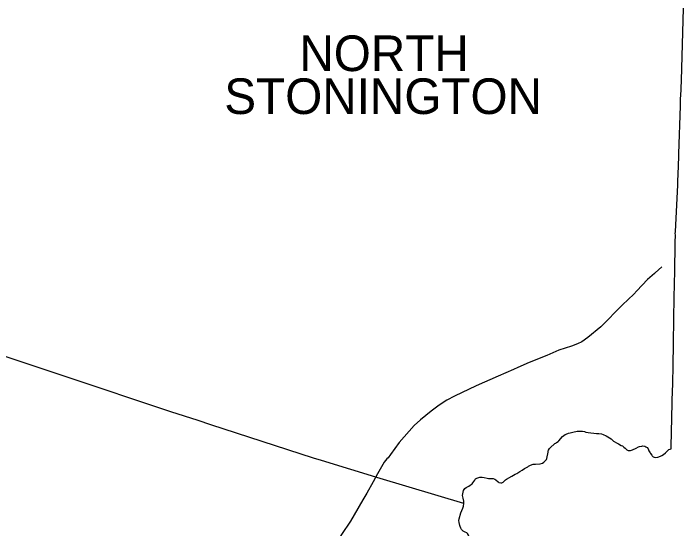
# Model space of a CAD drawing. Extents: x 0 to 2603, y -226 to 830.
# Drawn here: x 335.14 to 360.53, y 555.47 to 575 of the extents above; entities that cross this region are included whole.
import ezdxf

# ---------------------------------------------------------------- set-up
doc = ezdxf.new("R2010")
doc.units = 0
for name, color, linetype in [('CT_TSH_Map_Interstate_Roads', 7, 'Continuous'), ('CT_TSH_Map_Town_Limits', 7, 'Continuous'), ('CT_TSH_Map_Town_Text', 7, 'Continuous')]:
    doc.layers.add(name, color=color, linetype=linetype)

msp = doc.modelspace()

# ---------------------------------------------------------------- linework, layer by layer
at = {"layer": 'CT_TSH_Map_Interstate_Roads'}
for points in [[(359.7, 565.398), (359.443, 565.161)], [(359.418, 565.136), (359.163, 564.91)], [(359.443, 565.161), (359.418, 565.136)], [(359.163, 564.91), (358.756, 564.484)], [(358.756, 564.484), (358.636, 564.358)], [(358.636, 564.358), (358.209, 563.951), (357.386, 563.121), (356.902, 562.709)], [(356.902, 562.709), (356.667, 562.552)], [(356.504, 562.475), (356.283, 562.39), (355.797, 562.233), (355.343, 562.033), (354.681, 561.761), (354.249, 561.577)], [(356.667, 562.552), (356.504, 562.475)], [(354.249, 561.577), (354.077, 561.497), (353.501, 561.254), (352.668, 560.887), (351.846, 560.488)], [(351.846, 560.488), (351.558, 560.338), (351.267, 560.147)], [(351.267, 560.147), (350.959, 559.919), (350.555, 559.596)], [(350.555, 559.596), (350.323, 559.377)], [(350.323, 559.377), (349.748, 558.73), (349.425, 558.287), (349.338, 558.157)], [(349.338, 558.157), (349.286, 558.119), (349.185, 557.986)], [(349.185, 557.986), (348.929, 557.546)], [(348.929, 557.546), (348.762, 557.25), (348.523, 556.811)], [(348.523, 556.811), (348.38, 556.557), (348.05, 556)], [(348.05, 556), (347.903, 555.761), (347.571, 555.245), (347.381, 554.938), (347.147, 554.608)]]:
    msp.add_lwpolyline(points, dxfattribs=at)
at = {"layer": 'CT_TSH_Map_Town_Limits'}
for points in [[(358.974, 558.607), (359.059, 558.599), (359.101, 558.577), (359.142, 558.544), (359.177, 558.498), (359.209, 558.425), (359.256, 558.349), (359.269, 558.318), (359.325, 558.257), (359.337, 558.23), (359.354, 558.205), (359.375, 558.189), (359.411, 558.174), (359.458, 558.169), (359.547, 558.178), (359.651, 558.214), (359.696, 558.245), (359.769, 558.286), (359.844, 558.339), (359.9, 558.41), (359.923, 558.428), (359.961, 558.472), (360.016, 558.489), (360.056, 558.497), (360.058, 558.549), (360.055, 558.589), (360.106, 560.771), (360.114, 560.861), (360.128, 561.773), (360.143, 562.36), (360.141, 562.478), (360.149, 562.523), (360.15, 563.385), (360.157, 563.501), (360.178, 564.807), (360.191, 565.167), (360.206, 566.319), (360.217, 566.61), (360.212, 566.652), (360.225, 566.724), (360.313, 568.504), (360.311, 568.655), (360.324, 568.891), (360.345, 569.57), (360.339, 569.6), (360.349, 569.67), (360.405, 571.494), (360.414, 571.623), (360.414, 571.754), (360.409, 571.799), (360.416, 571.86), (360.442, 572.459), (360.525, 575.194)], [(352.196, 556.418), (349.026, 557.372), (346.803, 558.055), (346.503, 558.148), (342.62, 559.406), (342.136, 559.565), (341.106, 559.901), (337.099, 561.235), (334.314, 562.16)], [(352.196, 556.418), (352.198, 556.458), (352.194, 556.513), (352.171, 556.626), (352.154, 556.729), (352.171, 556.854), (352.192, 556.913), (352.211, 556.954), (352.239, 556.997), (352.29, 557.036), (352.384, 557.082), (352.438, 557.12), (352.484, 557.145), (352.521, 557.174), (352.536, 557.206), (352.618, 557.303), (352.648, 557.354), (352.694, 557.389), (352.804, 557.422), (352.844, 557.425), (352.896, 557.421), (352.968, 557.404), (352.974, 557.404), (353.09, 557.384), (353.129, 557.377), (353.268, 557.372), (353.305, 557.37), (353.37, 557.351), (353.409, 557.321), (353.501, 557.24), (353.53, 557.219), (353.599, 557.203), (353.642, 557.211), (353.689, 557.234), (353.776, 557.316), (353.819, 557.346), (354.024, 557.458), (354.148, 557.536), (354.21, 557.561), (354.317, 557.64), (354.409, 557.688), (354.493, 557.745), (354.621, 557.818), (354.656, 557.835), (354.697, 557.865), (354.793, 557.907), (354.831, 557.919), (354.918, 557.919), (355.092, 557.931), (355.176, 557.954), (355.232, 557.992), (355.316, 558.077), (355.33, 558.096), (355.348, 558.135), (355.394, 558.366), (355.397, 558.402), (355.406, 558.444), (355.444, 558.51), (355.5, 558.561), (355.626, 558.669), (355.652, 558.695), (355.682, 558.716), (355.712, 558.73), (355.774, 558.775), (355.805, 558.801), (355.944, 558.963), (356.045, 559.038), (356.134, 559.078), (356.166, 559.09), (356.225, 559.099), (356.329, 559.13), (356.496, 559.159), (356.597, 559.169), (356.699, 559.168), (356.77, 559.154), (356.827, 559.132), (356.904, 559.113), (357.227, 559.076), (357.313, 559.075), (357.418, 559.058), (357.481, 559.04), (357.595, 558.993), (357.778, 558.869), (357.796, 558.86), (357.876, 558.788), (358.003, 558.711), (358.064, 558.682), (358.157, 558.627), (358.212, 558.604), (358.264, 558.557), (358.313, 558.522), (358.373, 558.464), (358.395, 558.449), (358.428, 558.436), (358.508, 558.438), (358.59, 558.462), (358.734, 558.526), (358.814, 558.57), (358.859, 558.587), (358.938, 558.6), (358.974, 558.607)], [(352.41, 554.809), (352.396, 554.949), (352.394, 555.05), (352.386, 555.186), (352.376, 555.219), (352.337, 555.291), (352.316, 555.309), (352.246, 555.336), (352.179, 555.377), (352.113, 555.444), (352.085, 555.492), (352.065, 555.547), (352.054, 555.594), (352.02, 555.702), (352.016, 555.786), (352.022, 555.838), (352.085, 556.076), (352.119, 556.155), (352.164, 556.247), (352.188, 556.329), (352.196, 556.418)]]:
    msp.add_lwpolyline(points, dxfattribs=at)

# ---------------------------------------------------------------- texts
at = {"layer": 'CT_TSH_Map_Town_Text'}
for s, p in [('NORTH', (345.969, 572.81)), ('STONINGTON', (343.126, 571.183))]:
    msp.add_text(s, height=1.35, dxfattribs=at).set_placement(p)

doc.saveas('drawing.dxf')
